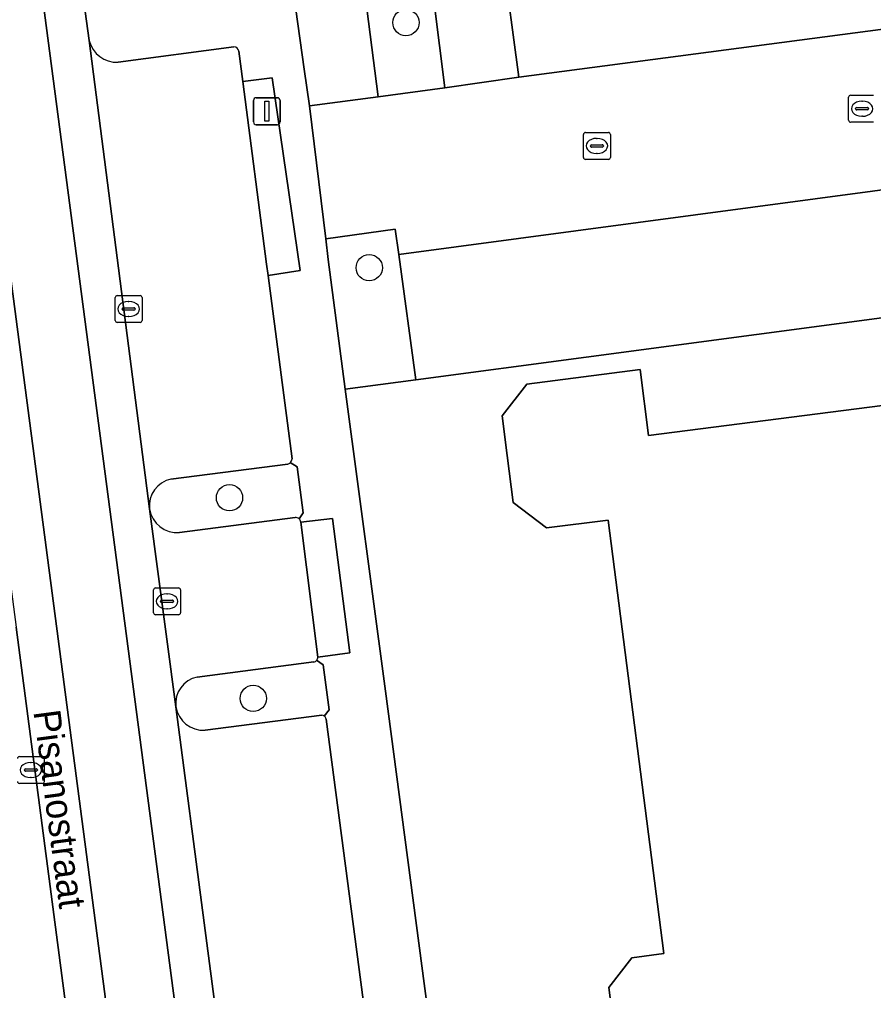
# Model space of a CAD drawing. Extents: x 160554 to 161248, y 385329 to 386506.
# Drawn here: x 161068.51 to 161100.28, y 386038.26 to 386074.38 of the extents above; entities that cross this region are included whole.
import ezdxf

# ---------------------------------------------------------------- set-up
doc = ezdxf.new("R2010")
doc.units = 0
for name, color, linetype in [('IMGEO_Boom', 7, 'Continuous'), ('IMGEO_Erf', 7, 'Continuous'), ('IMGEO_Groenvoorziening', 7, 'Continuous'), ('IMGEO_Kolk', 7, 'Continuous'), ('IMGEO_Lichtmast', 7, 'Continuous'), ('IMGEO_Openbare_ruimte_label', 7, 'Continuous'), ('IMGEO_Pand', 7, 'Continuous'), ('IMGEO_Parkeervlak_open', 7, 'Continuous'), ('IMGEO_Rijbaan_lokaal_gesloten', 7, 'Continuous'), ('IMGEO_Rijbaan_lokaal_open', 7, 'Continuous'), ('IMGEO_Voetpad_open', 7, 'Continuous')]:
    doc.layers.add(name, color=color, linetype=linetype)

msp = doc.modelspace()

# ---------------------------------------------------------------- linework, layer by layer
at = {"layer": 'IMGEO_Boom'}
for centre in [(161082.887, 386074.265), (161081.522, 386065.147), (161076.325, 386056.588), (161077.208, 386049.124)]:
    msp.add_circle(centre, 0.489, dxfattribs=at)
at = {"layer": 'IMGEO_Erf'}
for points in [[(161102.264, 386063.508), (161083.261, 386060.976), (161080.632, 386060.626), (161082.13, 386049.396), (161088.666, 386000)], [(161090.847, 386035.191), (161090.44, 386038.373), (161091.294, 386039.478), (161092.481, 386039.63), (161090.415, 386055.76), (161088.113, 386055.465), (161086.88, 386056.417), (161086.657, 386058.155), (161086.468, 386059.632), (161087.383, 386060.816), (161091.596, 386061.355), (161091.909, 386058.91), (161101.578, 386060.148)]]:
    msp.add_lwpolyline(points, dxfattribs=at)
at = {"layer": 'IMGEO_Groenvoorziening'}
for points in [[(161078.317, 386078.134), (161079.106, 386072.535), (161079.298, 386071.172), (161081.857, 386071.497), (161081.264, 386076.158)], [(161083.748, 386076.474), (161084.336, 386071.84), (161087.092, 386072.236), (161086.483, 386076.783)], [(161078.491, 386057.838), (161074.147, 386057.281)], [(161078.915, 386055.807), (161079.065, 386056.023), (161078.842, 386057.733), (161078.586, 386057.897)], [(161074.469, 386055.299), (161078.77, 386055.854)], [(161079.458, 386050.479), (161075.122, 386049.918)], [(161079.852, 386048.467), (161080.026, 386048.703), (161079.815, 386050.374), (161079.567, 386050.543)], [(161075.42, 386047.944), (161079.76, 386048.499)]]:
    msp.add_lwpolyline(points, dxfattribs=at)
msp.add_lwpolyline([(161082.621, 386065.643), (161082.492, 386066.584), (161079.91, 386066.216), (161079.989, 386065.451), (161080.632, 386060.626), (161083.261, 386060.976)], close=True, dxfattribs=at)
for centre, radius, start, end in [((161078.414, 386058.068), 0.243, 288.5429, 315.142), ((161074.349, 386056.299), 1.003, 101.6364, 186.9352), ((161074.373, 386056.324), 1.03, 188.1692, 275.3305), ((161078.789, 386055.667), 0.188, 48.1365, 95.9445), ((161079.427, 386050.657), 0.181, 279.9546, 320.8846), ((161075.325, 386048.939), 1, 101.7069, 187.1391), ((161075.348, 386048.967), 1.026, 188.5401, 274.0503), ((161079.754, 386048.332), 0.167, 53.8434, 87.7986)]:
    msp.add_arc(centre, radius, start, end, dxfattribs=at)
at = {"layer": 'IMGEO_Kolk'}
for p, q in [((161099.355, 386070.633), (161099.355, 386071.485)), ((161099.43, 386071.559), (161100.282, 386071.559)), ((161099.843, 386071.339), (161099.868, 386071.339)), ((161099.614, 386071.053), (161099.614, 386071.065)), ((161100.052, 386071.016), (161099.654, 386071.016)), ((161099.657, 386071.102), (161100.055, 386071.102)), ((161100.098, 386071.065), (161100.098, 386071.053)), ((161100.282, 386070.559), (161099.43, 386070.559)), ((161099.866, 386070.779), (161099.841, 386070.779)), ((161089.49, 386069.25), (161089.49, 386070.102)), ((161089.565, 386070.176), (161090.417, 386070.176)), ((161089.978, 386069.956), (161090.003, 386069.956)), ((161090.491, 386070.102), (161090.491, 386069.25)), ((161089.749, 386069.67), (161089.749, 386069.682)), ((161090.187, 386069.633), (161089.789, 386069.633)), ((161089.792, 386069.719), (161090.19, 386069.719)), ((161090.233, 386069.682), (161090.233, 386069.67)), ((161090.417, 386069.176), (161089.565, 386069.176)), ((161090.001, 386069.396), (161089.976, 386069.396)), ((161072.148, 386064.11), (161073, 386064.11)), ((161072.073, 386063.184), (161072.073, 386064.036)), ((161072.561, 386063.89), (161072.586, 386063.89)), ((161073.074, 386064.036), (161073.074, 386063.184)), ((161072.332, 386063.604), (161072.332, 386063.616)), ((161072.77, 386063.567), (161072.372, 386063.567)), ((161072.375, 386063.653), (161072.773, 386063.653)), ((161072.584, 386063.33), (161072.559, 386063.33)), ((161072.816, 386063.616), (161072.816, 386063.604)), ((161073, 386063.11), (161072.148, 386063.11)), ((161073.577, 386053.236), (161074.429, 386053.236)), ((161073.502, 386052.31), (161073.502, 386053.162)), ((161073.99, 386053.016), (161074.015, 386053.016)), ((161074.503, 386053.162), (161074.503, 386052.31)), ((161073.761, 386052.73), (161073.761, 386052.742)), ((161074.199, 386052.693), (161073.801, 386052.693)), ((161073.804, 386052.779), (161074.202, 386052.779)), ((161074.245, 386052.742), (161074.245, 386052.73)), ((161074.429, 386052.236), (161073.577, 386052.236)), ((161074.013, 386052.456), (161073.988, 386052.456)), ((161068.511, 386046.96), (161069.363, 386046.96)), ((161068.924, 386046.74), (161068.949, 386046.74)), ((161069.437, 386046.886), (161069.437, 386046.034)), ((161068.695, 386046.454), (161068.695, 386046.466)), ((161069.133, 386046.417), (161068.735, 386046.417)), ((161068.738, 386046.503), (161069.136, 386046.503)), ((161069.179, 386046.466), (161069.179, 386046.454)), ((161068.947, 386046.18), (161068.922, 386046.18)), ((161069.363, 386045.96), (161068.511, 386045.96))]:
    msp.add_line(p, q, dxfattribs=at)
for points in [[(161099.355, 386070.633), (161099.355, 386071.485)], [(161099.43, 386071.559), (161100.282, 386071.559)], [(161100.282, 386070.559), (161099.43, 386070.559)], [(161089.49, 386069.25), (161089.49, 386070.102)], [(161089.565, 386070.176), (161090.417, 386070.176)], [(161090.491, 386070.102), (161090.491, 386069.25)], [(161090.417, 386069.176), (161089.565, 386069.176)], [(161072.148, 386064.11), (161073, 386064.11)], [(161072.073, 386063.184), (161072.073, 386064.036)], [(161073.074, 386064.036), (161073.074, 386063.184)], [(161073, 386063.11), (161072.148, 386063.11)], [(161073.577, 386053.236), (161074.429, 386053.236)], [(161073.502, 386052.31), (161073.502, 386053.162)], [(161074.503, 386053.162), (161074.503, 386052.31)], [(161074.429, 386052.236), (161073.577, 386052.236)], [(161068.511, 386046.96), (161069.363, 386046.96)], [(161069.437, 386046.886), (161069.437, 386046.034)], [(161069.363, 386045.96), (161068.511, 386045.96)]]:
    msp.add_lwpolyline(points, dxfattribs=at)
for centre, radius, start, end in [((161099.432, 386071.483), 0.0765, 91.552, 178.448), ((161099.432, 386071.483), 0.0765, 91.552, 178.448), ((161099.654, 386071.062), 0.0403, 85.8775, 175.7526), ((161099.651, 386071.052), 0.0366, 178.938, 274.7102), ((161100.055, 386071.059), 0.043, 264.8664, 352.4533), ((161100.059, 386071.064), 0.0386, 1.7309, 96.639), ((161099.432, 386070.635), 0.0765, 181.552, 268.448), ((161099.432, 386070.635), 0.0765, 181.552, 268.448), ((161089.567, 386070.1), 0.0765, 91.552, 178.448), ((161089.567, 386070.1), 0.0765, 91.552, 178.448), ((161090.415, 386070.1), 0.0765, 1.552, 88.448), ((161090.415, 386070.1), 0.0765, 1.552, 88.448), ((161089.789, 386069.679), 0.0403, 85.8775, 175.7526), ((161089.786, 386069.669), 0.0366, 178.938, 274.7102), ((161090.19, 386069.676), 0.043, 264.8664, 352.4533), ((161090.194, 386069.681), 0.0386, 1.7309, 96.639), ((161089.567, 386069.252), 0.0765, 181.552, 268.448), ((161089.567, 386069.252), 0.0765, 181.552, 268.448), ((161090.415, 386069.252), 0.0765, 271.552, 358.448), ((161090.415, 386069.252), 0.0765, 271.552, 358.448), ((161072.15, 386064.034), 0.0765, 91.552, 178.448), ((161072.15, 386064.034), 0.0765, 91.552, 178.448), ((161072.998, 386064.034), 0.0765, 1.552, 88.448), ((161072.998, 386064.034), 0.0765, 1.552, 88.448), ((161072.372, 386063.613), 0.0403, 85.8775, 175.7526), ((161072.369, 386063.603), 0.0366, 178.938, 274.7102), ((161072.773, 386063.61), 0.043, 264.8664, 352.4533), ((161072.777, 386063.615), 0.0386, 1.7309, 96.639), ((161072.15, 386063.186), 0.0765, 181.552, 268.448), ((161072.15, 386063.186), 0.0765, 181.552, 268.448), ((161072.998, 386063.186), 0.0765, 271.552, 358.448), ((161072.998, 386063.186), 0.0765, 271.552, 358.448), ((161073.579, 386053.16), 0.0765, 91.552, 178.448), ((161073.579, 386053.16), 0.0765, 91.552, 178.448), ((161074.427, 386053.16), 0.0765, 1.552, 88.448), ((161074.427, 386053.16), 0.0765, 1.552, 88.448), ((161073.801, 386052.739), 0.0403, 85.8775, 175.7526), ((161073.798, 386052.729), 0.0366, 178.938, 274.7102), ((161074.202, 386052.736), 0.043, 264.8664, 352.4533), ((161074.206, 386052.741), 0.0386, 1.7309, 96.639), ((161073.579, 386052.312), 0.0765, 181.552, 268.448), ((161073.579, 386052.312), 0.0765, 181.552, 268.448), ((161074.427, 386052.312), 0.0765, 271.552, 358.448), ((161074.427, 386052.312), 0.0765, 271.552, 358.448), ((161068.513, 386046.884), 0.0765, 91.552, 178.448), ((161068.513, 386046.884), 0.0765, 91.552, 178.448), ((161069.361, 386046.884), 0.0765, 1.552, 88.448), ((161069.361, 386046.884), 0.0765, 1.552, 88.448), ((161068.735, 386046.463), 0.0403, 85.8775, 175.7526), ((161068.732, 386046.453), 0.0366, 178.938, 274.7102), ((161069.136, 386046.46), 0.043, 264.8664, 352.4533), ((161069.14, 386046.465), 0.0386, 1.7309, 96.639), ((161068.513, 386046.036), 0.0765, 181.552, 268.448), ((161068.513, 386046.036), 0.0765, 181.552, 268.448), ((161069.361, 386046.036), 0.0765, 271.552, 358.448), ((161069.361, 386046.036), 0.0765, 271.552, 358.448)]:
    msp.add_arc(centre, radius, start, end, dxfattribs=at)
for centre, major_axis, ratio, start_param, end_param in [((161099.842, 386071.059), (-0.387, 0.002), 0.722429, 4.712389, 7.853982), ((161099.867, 386071.059), (-0.39, 0.002), 0.717154, 1.570796, 4.712389), ((161089.977, 386069.676), (-0.387, 0.002), 0.722429, 4.712389, 7.853982), ((161090.002, 386069.676), (-0.39, 0.002), 0.717154, 1.570796, 4.712389), ((161072.56, 386063.61), (-0.387, 0.002), 0.722429, 4.712389, 7.853982), ((161072.585, 386063.61), (-0.39, 0.002), 0.717154, 1.570796, 4.712389), ((161073.989, 386052.736), (-0.387, 0.002), 0.722429, 4.712389, 7.853982), ((161074.014, 386052.736), (-0.39, 0.002), 0.717154, 1.570796, 4.712389), ((161068.923, 386046.46), (-0.387, 0.002), 0.722429, 4.712389, 7.853982), ((161068.948, 386046.46), (-0.39, 0.002), 0.717154, 1.570796, 4.712389)]:
    msp.add_ellipse(centre, major_axis=major_axis, ratio=ratio, start_param=start_param, end_param=end_param, dxfattribs=at)
at = {"layer": 'IMGEO_Lichtmast'}
for p, q in [((161077.217, 386070.567), (161077.217, 386071.367)), ((161077.217, 386071.367), (161077.217, 386070.567)), ((161077.317, 386071.467), (161078.107, 386071.467)), ((161078.107, 386071.467), (161077.317, 386071.467)), ((161078.207, 386071.367), (161078.207, 386070.567)), ((161078.207, 386070.567), (161078.207, 386071.367)), ((161078.107, 386070.467), (161077.317, 386070.467)), ((161077.317, 386070.467), (161078.107, 386070.467))]:
    msp.add_line(p, q, dxfattribs=at)
msp.add_lwpolyline([(161077.637, 386071.342), (161077.787, 386071.342), (161077.787, 386070.592), (161077.637, 386070.592), (161077.637, 386071.342)], dxfattribs=at)
for centre, start, end in [((161077.317, 386071.367), 90, 180), ((161077.317, 386071.367), 90, 180), ((161078.107, 386071.367), 0, 90), ((161078.107, 386071.367), 360, 90), ((161077.317, 386070.567), 180, 270), ((161077.317, 386070.567), 180, 270), ((161078.107, 386070.567), 270, 0), ((161078.107, 386070.567), 270, 0)]:
    msp.add_arc(centre, 0.1, start, end, dxfattribs=at)
at = {"layer": 'IMGEO_Pand'}
msp.add_lwpolyline([(161101.578, 386060.148), (161091.909, 386058.91), (161091.596, 386061.355), (161087.383, 386060.816), (161086.468, 386059.632), (161086.657, 386058.155), (161086.88, 386056.417), (161088.113, 386055.465), (161090.415, 386055.76), (161092.481, 386039.63), (161091.294, 386039.478), (161090.44, 386038.373), (161090.847, 386035.191)], dxfattribs=at)
at = {"layer": 'IMGEO_Parkeervlak_open'}
for points in [[(161110.505, 386075.334), (161109.869, 386079.959), (161086.483, 386076.783), (161087.092, 386072.236)], [(161084.336, 386071.84), (161083.748, 386076.474), (161081.264, 386076.158), (161081.857, 386071.497)], [(161111.278, 386069.467), (161082.621, 386065.643), (161083.261, 386060.976), (161102.264, 386063.508), (161111.878, 386064.789)]]:
    msp.add_lwpolyline(points, close=True, dxfattribs=at)
for points in [[(161071.106, 386073.6), (161073.354, 386056.178)], [(161076.49, 386073.358), (161072.183, 386072.788)], [(161076.82, 386072.067), (161076.672, 386073.199)], [(161078.65, 386058.031), (161077.761, 386064.862), (161077.707, 386065.282), (161076.82, 386072.067)], [(161074.147, 386057.281), (161078.491, 386057.838)], [(161081.581, 385937.098), (161083.425, 385937.348), (161074.169, 386007.952), (161074.015, 386008.997), (161073.237, 386014.893), (161073.09, 386015.931), (161068.384, 386051.777)], [(161074.333, 386048.815), (161078.548, 386016.673)], [(161079.76, 386048.499), (161075.42, 386047.944)], [(161083.856, 386018.526), (161079.923, 386048.351)]]:
    msp.add_lwpolyline(points, dxfattribs=at)
for centre, radius, start, end in [((161072.135, 386073.845), 1.058, 193.3709, 272.6004), ((161076.493, 386073.178), 0.18, 6.8139, 90.9035), ((161078.418, 386058.06), 0.234, 315.9873, 352.9533), ((161078.414, 386058.068), 0.243, 288.5429, 315.142), ((161074.349, 386056.299), 1.003, 101.6364, 186.9352), ((161075.348, 386048.967), 1.026, 188.5401, 274.0503), ((161079.754, 386048.332), 0.167, 53.8434, 87.7986), ((161079.747, 386048.323), 0.178, 9.0725, 53.8665)]:
    msp.add_arc(centre, radius, start, end, dxfattribs=at)
at = {"layer": 'IMGEO_Rijbaan_lokaal_gesloten'}
for points in [[(161065.335, 386075.084), (161065.354, 386074.934), (161066.618, 386065.254), (161066.623, 386065.212), (161066.918, 386062.96), (161067.093, 386061.671), (161067.992, 386054.799), (161068.384, 386051.777), (161073.09, 386015.931), (161074.577, 386016.14), (161066.82, 386075.134)], [(161069.383, 386075.101), (161077.097, 386016.484), (161078.548, 386016.673), (161074.333, 386048.815), (161073.354, 386056.178), (161071.106, 386073.6)], [(161071.106, 386073.6), (161070.96, 386074.678)]]:
    msp.add_lwpolyline(points, dxfattribs=at)
at = {"layer": 'IMGEO_Rijbaan_lokaal_open'}
msp.add_lwpolyline([(161111.278, 386069.467), (161110.505, 386075.334), (161087.092, 386072.236), (161084.336, 386071.84), (161081.857, 386071.497), (161079.298, 386071.172), (161079.91, 386066.216), (161082.492, 386066.584), (161082.621, 386065.643)], close=True, dxfattribs=at)
for points in [[(161066.82, 386075.134), (161074.577, 386016.14), (161077.097, 386016.484), (161069.383, 386075.101)], [(161073.354, 386056.178), (161074.333, 386048.815)], [(161078.77, 386055.854), (161074.469, 386055.299)], [(161079.606, 386050.664), (161078.977, 386055.684)], [(161075.122, 386049.918), (161079.458, 386050.479)]]:
    msp.add_lwpolyline(points, dxfattribs=at)
for centre, radius, start, end in [((161074.373, 386056.324), 1.03, 188.1692, 275.3305), ((161078.789, 386055.667), 0.188, 48.1365, 95.9445), ((161078.791, 386055.668), 0.186, 5.0643, 48.4378), ((161079.427, 386050.657), 0.181, 279.9546, 320.8846), ((161079.432, 386050.653), 0.174, 320.7202, 3.5501), ((161075.325, 386048.939), 1, 101.7069, 187.1391)]:
    msp.add_arc(centre, radius, start, end, dxfattribs=at)
at = {"layer": 'IMGEO_Voetpad_open'}
for points in [[(161082.13, 386049.396), (161080.632, 386060.626), (161079.989, 386065.451), (161079.91, 386066.216), (161079.298, 386071.172), (161079.106, 386072.535), (161078.317, 386078.134), (161077.881, 386078.078), (161072.949, 386077.442), (161071.858, 386085.384), (161069.72, 386101.947), (161068.448, 386111.866), (161061.873, 386098.579)], [(161070.96, 386074.678), (161071.106, 386073.6)], [(161072.183, 386072.788), (161076.49, 386073.358)], [(161076.672, 386073.199), (161076.82, 386072.067), (161077.915, 386072.205), (161078.957, 386065.041), (161077.761, 386064.862), (161078.65, 386058.031)], [(161078.586, 386057.897), (161078.842, 386057.733), (161079.065, 386056.023), (161078.915, 386055.807)], [(161078.977, 386055.684), (161080.159, 386055.82), (161080.798, 386050.825), (161079.606, 386050.664)], [(161079.567, 386050.543), (161079.815, 386050.374), (161080.026, 386048.703), (161079.852, 386048.467)], [(161096.784, 385919.367), (161097.009, 385919.191), (161097.237, 385917.622), (161098.284, 385917.719), (161099.668, 385917.914), (161099.356, 385920.254), (161098.548, 385926.313), (161097.126, 385936.966), (161096.292, 385943.217), (161095.494, 385949.098), (161094.874, 385953.891), (161093.966, 385960.914), (161093.633, 385962.998), (161088.666, 386000), (161082.13, 386049.396)], [(161079.923, 386048.351), (161083.856, 386018.526)]]:
    msp.add_lwpolyline(points, dxfattribs=at)
for points in [[(161076.82, 386072.067), (161077.707, 386065.282), (161077.761, 386064.862), (161078.957, 386065.041), (161077.915, 386072.205)], [(161078.977, 386055.684), (161079.606, 386050.664), (161080.798, 386050.825), (161080.159, 386055.82)]]:
    msp.add_lwpolyline(points, close=True, dxfattribs=at)
for centre, radius, start, end in [((161072.135, 386073.845), 1.058, 193.3709, 272.6004), ((161076.493, 386073.178), 0.18, 6.8139, 90.9035), ((161078.418, 386058.06), 0.234, 315.9873, 352.9533), ((161078.791, 386055.668), 0.186, 5.0643, 48.4378), ((161079.432, 386050.653), 0.174, 320.7202, 3.5501), ((161079.747, 386048.323), 0.178, 9.0725, 53.8665)]:
    msp.add_arc(centre, radius, start, end, dxfattribs=at)

# ---------------------------------------------------------------- texts
at = {"layer": 'IMGEO_Openbare_ruimte_label'}
msp.add_text('Pisanostraat', height=1, rotation=277.5303, dxfattribs=at).set_placement((161069.028, 386048.636))

doc.saveas('drawing.dxf')
